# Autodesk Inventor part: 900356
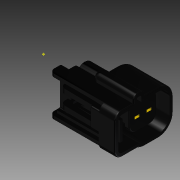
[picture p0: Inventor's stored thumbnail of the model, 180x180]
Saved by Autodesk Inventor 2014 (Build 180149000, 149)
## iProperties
Created: 2007-12
Part Number: 900356
Document SubType Name: Modeling
Designer: SW
Density: 1.06 g/cm^3
Categories: <MemberInstance><Categories><Category DisplayName="" Mnemonic="CABLEANDHARNESS" InternalName="e4a7e005-5e42-4d16-b293-125e7f0d0512"><Category DisplayName="" Mne
Mass: 6.1454 g
Surface Area: 63.7869 cm^2
Volume: 5.79754 cm^3
Material: ABS Plastic
Description: M60 POWER WIRE CONNECTOR
Appearance: Glossy - Black
GlobalPropertyList: <PropertyList/>
Component Category: Electrical
Author: SW
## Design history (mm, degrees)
feature "Base1"
sketch "Pin_Position"
  geometry: L1 (-2.064, 3.449)-(-3.257, 5.055) reference; L2 (-2.454, 5.651)-(-1.262, 4.046) reference; L3 (0.917, -0.564)-(-0.275, 1.041) reference; L4 (0.527, 1.638)-(1.72, 0.032) reference; L5 (-1.858, 4.848)-(-2.661, 4.252); L6 (1.124, 0.835)-(0.321, 0.239); 3 further points
  constraints: 6 midpoint, 4 end point
node "1"
node "2"
workpoint "Work Point3"
body "Solid1"
